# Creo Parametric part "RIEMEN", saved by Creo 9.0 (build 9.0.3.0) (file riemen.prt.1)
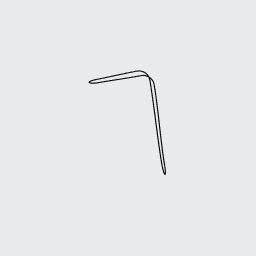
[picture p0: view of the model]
Units: millimeter Kilogram Sec (mmKs); MM, KILOGRAM, SECS
Materials in the file: STAHL

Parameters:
  COPY_GEOM_ORIGIN_TYPE = "Part"
  WERKSTOFF = "Stahl"
  ERSTELLER = "ARINDA"
  BENENNUNG = "XXX"
  TEILETYP = "K"
  PTC_MASTER_MATERIAL = "STAHL"

Other parameters: MASSE

Created from: ARINDA_STARTTEIL.PRT

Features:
  1. coordinate system
  2. datum plane "RECHTS_Y-Z"
  3. datum plane "OBEN_X-Z"
  4. datum plane "VORNE_X-Y"
  5. datum axis
  6. datum axis
  7. datum axis
  8. datum point "PNT0"
  9. feature "Kopie-geometrie ID 40"
  10. feature "Kopie-geometrie ID 62"
  11. feature "Kopie-geometrie ID 82"
  12. feature "Kopie-geometrie ID 102"
  13. datum plane "DTM1"
  14. datum plane "DTM2"
  15. sketch "Skizze 1"
  16. sketch "Skizze 2"
  17. datum plane "DTM3"
  18. sketch "Skizze 3"
  19. sketch "Skizze 4"
  20. datum plane "DTM4"
  21. sketch "Skizze 5"
  22. sketch "Skizze 6"
  23. sketch "Skizze 7"
  24. curve "Schneiden 1"
  25. datum curve "Trimmen 1"
  26. datum curve "Trimmen 2"
  27. datum plane "DTM5"
  28. sketch "Skizze 8"
  29. datum curve "Kurve 1"
  30. datum curve "Kurve 2"
  31. protrusion "Ziehen 1"
  32. mirror "Spiegeln 1"

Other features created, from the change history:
  coordinate system "CS1"

Other named items: RECHTS_Y-Z_1, OBEN_X-Z_1, VORNE_X-Y_1, DTM1_1, DTM2_1, DTM3_1, DTM4_1, DTM5_1, A_X, A_Y, A_Z, A_X_1, A_Z_1, A_Z_2, A_X_3, A_Y_2, A_Z_4, A_X_1_2, A_Z_1_2, A_Z_2_2, CS0, CS0_2, PNT0_2, PNT1_2, PNT2_2, PNT3_2, PNT4_2

Layers: 01_ACHSEN, 01_ACHSEN_STD, 01_EBENEN, 01_EBENEN_STD, 01_KOORDSYS_STD, 01_KURVEN, 01_PUNKTE_STD, KURVENELEMENTE, SAMMELFLÄCHEN, VOLUMENGEOMETRIE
